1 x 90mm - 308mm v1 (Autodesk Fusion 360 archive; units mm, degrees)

design "1 x 90mm - 308mm" references "autodesk generic router xyz"
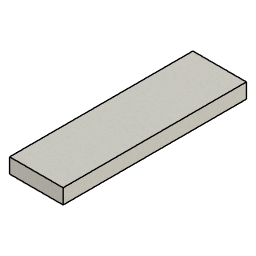
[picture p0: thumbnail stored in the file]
sketch "Sketch1" plane through (0, 0, 0) normal (0, 0, 1) x axis (1, 0, 0)
  line L1 (90, 0) -> (0, 0)
  line L2 (90, 308) -> (90, 0)
  line L3 (0, 308) -> (90, 308)
  line L4 (0, 0) -> (0, 308)
  point P1 (0, 0)
  point P2 (0, 0)
  point P3 (90, 0)
  point P5 (0, 308)
  horizontal L1
  vertical L2
  horizontal L3
  vertical L4
  coincident P1 P2
  dimension "d1" distance P2 P3 = 90
  dimension "d2" distance P2 P5 = 308
extrude "Extrude1" new body sketch "Sketch1" along normal blind 25

design "autodesk generic router xyz"
named bodies: "static", "x_axis_head", "y_axis_head", "z_axis_head"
